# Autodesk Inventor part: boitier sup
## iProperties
Author: robert
Shininess: 21.0
PropertySet Name: _Private Model Information
Compacted: True
Length Units: 11269
Angle Units: 11283
Time Units: 11279
Mass Units: 11290
Length Display Precision: 3
Angle Display Precision: 2
Created: 2001-07
Part Number: boitier sup
Material: Par défaut
Document SubType Name: Modélisation
Designer: robert
Control State: 0
Master: False
Checked Out: False
PropertySet Name: Design Tracking Control
Density: 0.0
Volumn: 0.0
Area: 0.0
PropertySet Name: Model Information
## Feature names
1. Extrusion1
2. Congé1 [Fillet]
3. Coque1
4. Extrusion2
5. Extrusion3
6. Extrusion4
7. Extrusion5
8. Congé2 [Fillet]
9. Congé3 [Fillet]
10. Congé4 [Fillet]
11. Congé5 [Fillet]
12. Congé6 [Fillet]
13. Congé7 [Fillet]
14. Congé8 [Fillet]
15. Congé9 [Fillet]
16. Congé10 [Fillet]
17. Congé11 [Fillet]
18. Congé12 [Fillet]
19. Perçage1 [Hole]
20. Extrusion6
21. Extrusion7
22. Extrusion8
